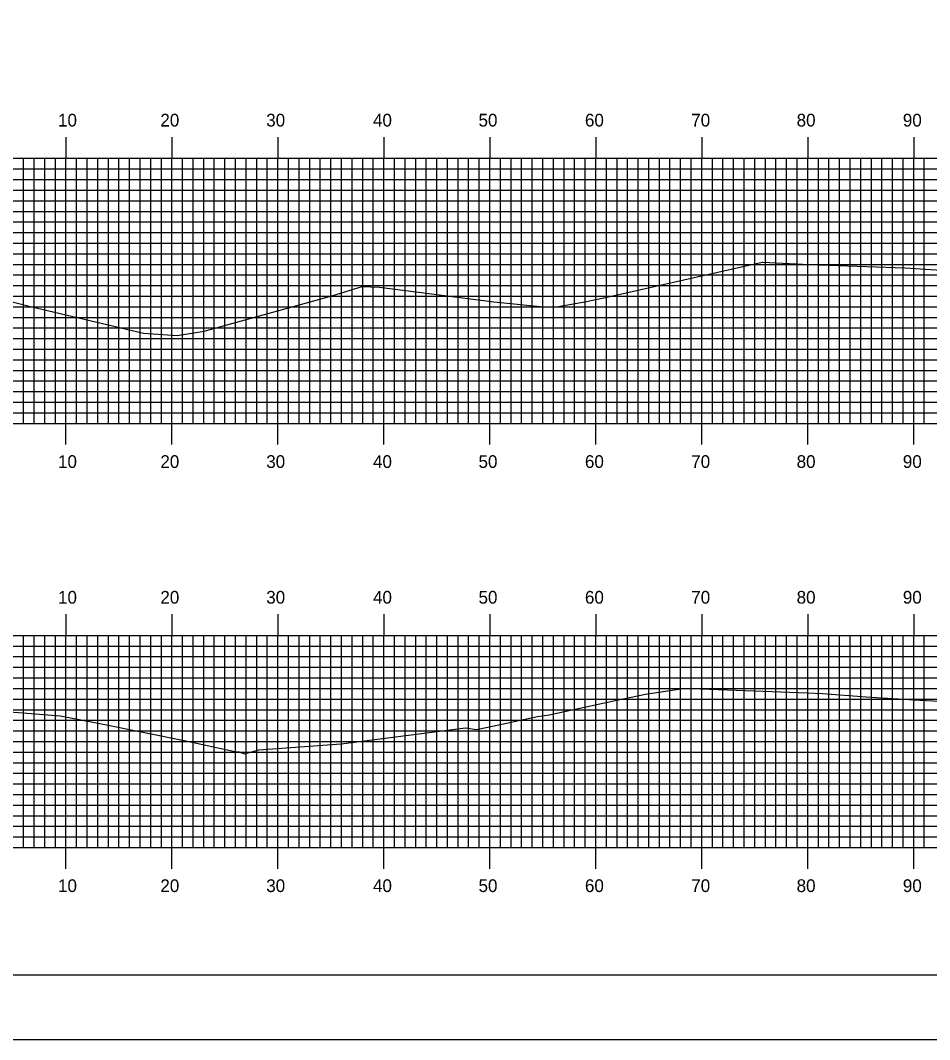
# Model space of a CAD drawing. Extents: x 855468 to 855811, y 366605 to 366825.
# Drawn here: x 855639.3 to 855725.1, y 366604.9 to 366701.1 of the extents above; entities that cross this region are included whole.
import ezdxf

# ---------------------------------------------------------------- set-up
doc = ezdxf.new("R2010")
doc.units = 0
for name, color, linetype in [('BORDER', 7, 'Continuous'), ('H_V ANNOTATION', 7, 'Continuous'), ('M_Roadway_Centerline', 7, 'Continuous'), ('MAJOR', 7, 'Continuous'), ('MINOR', 7, 'Continuous'), ('PLOT BOUNDARY', 7, 'Continuous'), ('S_Roadway_Centerline', 7, 'Continuous')]:
    doc.layers.add(name, color=color, linetype=linetype)

msp = doc.modelspace()

# ---------------------------------------------------------------- linework, layer by layer
at = {"layer": 'BORDER'}
msp.add_lwpolyline([(855483.982, 366611.055), (855803.982, 366611.055), (855803.982, 366821.055), (855483.982, 366821.055)], close=True, dxfattribs=at)
at = {"layer": 'MAJOR'}
for p, q in [((855643.582, 366690.059), (855643.582, 366688.055)), ((855653.582, 366690.059), (855653.582, 366688.055)), ((855663.582, 366690.059), (855663.582, 366688.055)), ((855673.582, 366690.059), (855673.582, 366688.055)), ((855683.582, 366690.059), (855683.582, 366688.055)), ((855693.582, 366690.059), (855693.582, 366688.055)), ((855703.582, 366690.059), (855703.582, 366688.055)), ((855713.582, 366690.059), (855713.582, 366688.055)), ((855723.582, 366690.059), (855723.582, 366688.055)), ((855493.582, 366688.055), (855773.582, 366688.055)), ((855493.582, 366688.055), (855773.582, 366688.055)), ((855643.582, 366663.055), (855643.582, 366688.055)), ((855653.582, 366663.055), (855653.582, 366688.055)), ((855663.582, 366663.055), (855663.582, 366688.055)), ((855673.582, 366663.055), (855673.582, 366688.055)), ((855683.582, 366663.055), (855683.582, 366688.055)), ((855693.582, 366663.055), (855693.582, 366688.055)), ((855703.582, 366663.055), (855703.582, 366688.055)), ((855713.582, 366663.055), (855713.582, 366688.055)), ((855723.582, 366663.055), (855723.582, 366688.055)), ((855493.582, 366683.055), (855773.582, 366683.055)), ((855493.582, 366678.055), (855773.582, 366678.055)), ((855493.582, 366673.055), (855773.582, 366673.055)), ((855493.582, 366668.055), (855773.582, 366668.055)), ((855493.582, 366663.055), (855773.582, 366663.055)), ((855493.582, 366663.055), (855773.582, 366663.055)), ((855643.582, 366661.051), (855643.582, 366663.055)), ((855653.582, 366661.051), (855653.582, 366663.055)), ((855663.582, 366661.051), (855663.582, 366663.055)), ((855673.582, 366661.051), (855673.582, 366663.055)), ((855683.582, 366661.051), (855683.582, 366663.055)), ((855693.582, 366661.051), (855693.582, 366663.055)), ((855703.582, 366661.051), (855703.582, 366663.055)), ((855713.582, 366661.051), (855713.582, 366663.055)), ((855723.582, 366661.051), (855723.582, 366663.055)), ((855643.582, 366645.059), (855643.582, 366643.055)), ((855653.582, 366645.059), (855653.582, 366643.055)), ((855663.582, 366645.059), (855663.582, 366643.055)), ((855673.582, 366645.059), (855673.582, 366643.055)), ((855683.582, 366645.059), (855683.582, 366643.055)), ((855693.582, 366645.059), (855693.582, 366643.055)), ((855703.582, 366645.059), (855703.582, 366643.055)), ((855713.582, 366645.059), (855713.582, 366643.055)), ((855723.582, 366645.059), (855723.582, 366643.055)), ((855493.582, 366643.055), (855773.582, 366643.055)), ((855493.582, 366643.055), (855773.582, 366643.055)), ((855643.582, 366623.055), (855643.582, 366643.055)), ((855653.582, 366623.055), (855653.582, 366643.055)), ((855663.582, 366623.055), (855663.582, 366643.055)), ((855673.582, 366623.055), (855673.582, 366643.055)), ((855683.582, 366623.055), (855683.582, 366643.055)), ((855693.582, 366623.055), (855693.582, 366643.055)), ((855703.582, 366623.055), (855703.582, 366643.055)), ((855713.582, 366623.055), (855713.582, 366643.055)), ((855723.582, 366623.055), (855723.582, 366643.055)), ((855493.582, 366638.055), (855773.582, 366638.055)), ((855493.582, 366633.055), (855773.582, 366633.055)), ((855493.582, 366628.055), (855773.582, 366628.055)), ((855493.582, 366623.055), (855773.582, 366623.055)), ((855493.582, 366623.055), (855773.582, 366623.055)), ((855643.582, 366621.051), (855643.582, 366623.055)), ((855653.582, 366621.051), (855653.582, 366623.055)), ((855663.582, 366621.051), (855663.582, 366623.055)), ((855673.582, 366621.051), (855673.582, 366623.055)), ((855683.582, 366621.051), (855683.582, 366623.055)), ((855693.582, 366621.051), (855693.582, 366623.055)), ((855703.582, 366621.051), (855703.582, 366623.055)), ((855713.582, 366621.051), (855713.582, 366623.055)), ((855723.582, 366621.051), (855723.582, 366623.055))]:
    msp.add_line(p, q, dxfattribs=at)
at = {"layer": 'MINOR'}
for p, q in [((855639.582, 366663.055), (855639.582, 366688.055)), ((855640.582, 366663.055), (855640.582, 366688.055)), ((855641.582, 366663.055), (855641.582, 366688.055)), ((855642.582, 366663.055), (855642.582, 366688.055)), ((855644.582, 366663.055), (855644.582, 366688.055)), ((855645.582, 366663.055), (855645.582, 366688.055)), ((855646.582, 366663.055), (855646.582, 366688.055)), ((855647.582, 366663.055), (855647.582, 366688.055)), ((855648.582, 366663.055), (855648.582, 366688.055)), ((855649.582, 366663.055), (855649.582, 366688.055)), ((855650.582, 366663.055), (855650.582, 366688.055)), ((855651.582, 366663.055), (855651.582, 366688.055)), ((855652.582, 366663.055), (855652.582, 366688.055)), ((855654.582, 366663.055), (855654.582, 366688.055)), ((855655.582, 366663.055), (855655.582, 366688.055)), ((855656.582, 366663.055), (855656.582, 366688.055)), ((855657.582, 366663.055), (855657.582, 366688.055)), ((855658.582, 366663.055), (855658.582, 366688.055)), ((855659.582, 366663.055), (855659.582, 366688.055)), ((855660.582, 366663.055), (855660.582, 366688.055)), ((855661.582, 366663.055), (855661.582, 366688.055)), ((855662.582, 366663.055), (855662.582, 366688.055)), ((855664.582, 366663.055), (855664.582, 366688.055)), ((855665.582, 366663.055), (855665.582, 366688.055)), ((855666.582, 366663.055), (855666.582, 366688.055)), ((855667.582, 366663.055), (855667.582, 366688.055)), ((855668.582, 366663.055), (855668.582, 366688.055)), ((855669.582, 366663.055), (855669.582, 366688.055)), ((855670.582, 366663.055), (855670.582, 366688.055)), ((855671.582, 366663.055), (855671.582, 366688.055)), ((855672.582, 366663.055), (855672.582, 366688.055)), ((855674.582, 366663.055), (855674.582, 366688.055)), ((855675.582, 366663.055), (855675.582, 366688.055)), ((855676.582, 366663.055), (855676.582, 366688.055)), ((855677.582, 366663.055), (855677.582, 366688.055)), ((855678.582, 366663.055), (855678.582, 366688.055)), ((855679.582, 366663.055), (855679.582, 366688.055)), ((855680.582, 366663.055), (855680.582, 366688.055)), ((855681.582, 366663.055), (855681.582, 366688.055)), ((855682.582, 366663.055), (855682.582, 366688.055)), ((855684.582, 366663.055), (855684.582, 366688.055)), ((855685.582, 366663.055), (855685.582, 366688.055)), ((855686.582, 366663.055), (855686.582, 366688.055)), ((855687.582, 366663.055), (855687.582, 366688.055)), ((855688.582, 366663.055), (855688.582, 366688.055)), ((855689.582, 366663.055), (855689.582, 366688.055)), ((855690.582, 366663.055), (855690.582, 366688.055)), ((855691.582, 366663.055), (855691.582, 366688.055)), ((855692.582, 366663.055), (855692.582, 366688.055)), ((855694.582, 366663.055), (855694.582, 366688.055)), ((855695.582, 366663.055), (855695.582, 366688.055)), ((855696.582, 366663.055), (855696.582, 366688.055)), ((855697.582, 366663.055), (855697.582, 366688.055)), ((855698.582, 366663.055), (855698.582, 366688.055)), ((855699.582, 366663.055), (855699.582, 366688.055)), ((855700.582, 366663.055), (855700.582, 366688.055)), ((855701.582, 366663.055), (855701.582, 366688.055)), ((855702.582, 366663.055), (855702.582, 366688.055)), ((855704.582, 366663.055), (855704.582, 366688.055)), ((855705.582, 366663.055), (855705.582, 366688.055)), ((855706.582, 366663.055), (855706.582, 366688.055)), ((855707.582, 366663.055), (855707.582, 366688.055)), ((855708.582, 366663.055), (855708.582, 366688.055)), ((855709.582, 366663.055), (855709.582, 366688.055)), ((855710.582, 366663.055), (855710.582, 366688.055)), ((855711.582, 366663.055), (855711.582, 366688.055)), ((855712.582, 366663.055), (855712.582, 366688.055)), ((855714.582, 366663.055), (855714.582, 366688.055)), ((855715.582, 366663.055), (855715.582, 366688.055)), ((855716.582, 366663.055), (855716.582, 366688.055)), ((855717.582, 366663.055), (855717.582, 366688.055)), ((855718.582, 366663.055), (855718.582, 366688.055)), ((855719.582, 366663.055), (855719.582, 366688.055)), ((855720.582, 366663.055), (855720.582, 366688.055)), ((855721.582, 366663.055), (855721.582, 366688.055)), ((855722.582, 366663.055), (855722.582, 366688.055)), ((855724.582, 366663.055), (855724.582, 366688.055)), ((855493.582, 366687.055), (855773.582, 366687.055)), ((855493.582, 366686.055), (855773.582, 366686.055)), ((855493.582, 366685.055), (855773.582, 366685.055)), ((855493.582, 366684.055), (855773.582, 366684.055)), ((855493.582, 366682.055), (855773.582, 366682.055)), ((855493.582, 366681.055), (855773.582, 366681.055)), ((855493.582, 366680.055), (855773.582, 366680.055)), ((855493.582, 366679.055), (855773.582, 366679.055)), ((855493.582, 366677.055), (855773.582, 366677.055)), ((855493.582, 366676.055), (855773.582, 366676.055)), ((855493.582, 366675.055), (855773.582, 366675.055)), ((855493.582, 366674.055), (855773.582, 366674.055)), ((855493.582, 366672.055), (855773.582, 366672.055)), ((855493.582, 366671.055), (855773.582, 366671.055)), ((855493.582, 366670.055), (855773.582, 366670.055)), ((855493.582, 366669.055), (855773.582, 366669.055)), ((855493.582, 366667.055), (855773.582, 366667.055)), ((855493.582, 366666.055), (855773.582, 366666.055)), ((855493.582, 366665.055), (855773.582, 366665.055)), ((855493.582, 366664.055), (855773.582, 366664.055)), ((855639.582, 366623.055), (855639.582, 366643.055)), ((855640.582, 366623.055), (855640.582, 366643.055)), ((855641.582, 366623.055), (855641.582, 366643.055)), ((855642.582, 366623.055), (855642.582, 366643.055)), ((855644.582, 366623.055), (855644.582, 366643.055)), ((855645.582, 366623.055), (855645.582, 366643.055)), ((855646.582, 366623.055), (855646.582, 366643.055)), ((855647.582, 366623.055), (855647.582, 366643.055)), ((855648.582, 366623.055), (855648.582, 366643.055)), ((855649.582, 366623.055), (855649.582, 366643.055)), ((855650.582, 366623.055), (855650.582, 366643.055)), ((855651.582, 366623.055), (855651.582, 366643.055)), ((855652.582, 366623.055), (855652.582, 366643.055)), ((855654.582, 366623.055), (855654.582, 366643.055)), ((855655.582, 366623.055), (855655.582, 366643.055)), ((855656.582, 366623.055), (855656.582, 366643.055)), ((855657.582, 366623.055), (855657.582, 366643.055)), ((855658.582, 366623.055), (855658.582, 366643.055)), ((855659.582, 366623.055), (855659.582, 366643.055)), ((855660.582, 366623.055), (855660.582, 366643.055)), ((855661.582, 366623.055), (855661.582, 366643.055)), ((855662.582, 366623.055), (855662.582, 366643.055)), ((855664.582, 366623.055), (855664.582, 366643.055)), ((855665.582, 366623.055), (855665.582, 366643.055)), ((855666.582, 366623.055), (855666.582, 366643.055)), ((855667.582, 366623.055), (855667.582, 366643.055)), ((855668.582, 366623.055), (855668.582, 366643.055)), ((855669.582, 366623.055), (855669.582, 366643.055)), ((855670.582, 366623.055), (855670.582, 366643.055)), ((855671.582, 366623.055), (855671.582, 366643.055)), ((855672.582, 366623.055), (855672.582, 366643.055)), ((855674.582, 366623.055), (855674.582, 366643.055)), ((855675.582, 366623.055), (855675.582, 366643.055)), ((855676.582, 366623.055), (855676.582, 366643.055)), ((855677.582, 366623.055), (855677.582, 366643.055)), ((855678.582, 366623.055), (855678.582, 366643.055)), ((855679.582, 366623.055), (855679.582, 366643.055)), ((855680.582, 366623.055), (855680.582, 366643.055)), ((855681.582, 366623.055), (855681.582, 366643.055)), ((855682.582, 366623.055), (855682.582, 366643.055)), ((855684.582, 366623.055), (855684.582, 366643.055)), ((855685.582, 366623.055), (855685.582, 366643.055)), ((855686.582, 366623.055), (855686.582, 366643.055)), ((855687.582, 366623.055), (855687.582, 366643.055)), ((855688.582, 366623.055), (855688.582, 366643.055)), ((855689.582, 366623.055), (855689.582, 366643.055)), ((855690.582, 366623.055), (855690.582, 366643.055)), ((855691.582, 366623.055), (855691.582, 366643.055)), ((855692.582, 366623.055), (855692.582, 366643.055)), ((855694.582, 366623.055), (855694.582, 366643.055)), ((855695.582, 366623.055), (855695.582, 366643.055)), ((855696.582, 366623.055), (855696.582, 366643.055)), ((855697.582, 366623.055), (855697.582, 366643.055)), ((855698.582, 366623.055), (855698.582, 366643.055)), ((855699.582, 366623.055), (855699.582, 366643.055)), ((855700.582, 366623.055), (855700.582, 366643.055)), ((855701.582, 366623.055), (855701.582, 366643.055)), ((855702.582, 366623.055), (855702.582, 366643.055)), ((855704.582, 366623.055), (855704.582, 366643.055)), ((855705.582, 366623.055), (855705.582, 366643.055)), ((855706.582, 366623.055), (855706.582, 366643.055)), ((855707.582, 366623.055), (855707.582, 366643.055)), ((855708.582, 366623.055), (855708.582, 366643.055)), ((855709.582, 366623.055), (855709.582, 366643.055)), ((855710.582, 366623.055), (855710.582, 366643.055)), ((855711.582, 366623.055), (855711.582, 366643.055)), ((855712.582, 366623.055), (855712.582, 366643.055)), ((855714.582, 366623.055), (855714.582, 366643.055)), ((855715.582, 366623.055), (855715.582, 366643.055)), ((855716.582, 366623.055), (855716.582, 366643.055)), ((855717.582, 366623.055), (855717.582, 366643.055)), ((855718.582, 366623.055), (855718.582, 366643.055)), ((855719.582, 366623.055), (855719.582, 366643.055)), ((855720.582, 366623.055), (855720.582, 366643.055)), ((855721.582, 366623.055), (855721.582, 366643.055)), ((855722.582, 366623.055), (855722.582, 366643.055)), ((855724.582, 366623.055), (855724.582, 366643.055)), ((855493.582, 366642.055), (855773.582, 366642.055)), ((855493.582, 366641.055), (855773.582, 366641.055)), ((855493.582, 366640.055), (855773.582, 366640.055)), ((855493.582, 366639.055), (855773.582, 366639.055)), ((855493.582, 366637.055), (855773.582, 366637.055)), ((855493.582, 366636.055), (855773.582, 366636.055)), ((855493.582, 366635.055), (855773.582, 366635.055)), ((855493.582, 366634.055), (855773.582, 366634.055)), ((855493.582, 366632.055), (855773.582, 366632.055)), ((855493.582, 366631.055), (855773.582, 366631.055)), ((855493.582, 366630.055), (855773.582, 366630.055)), ((855493.582, 366629.055), (855773.582, 366629.055)), ((855493.582, 366627.055), (855773.582, 366627.055)), ((855493.582, 366626.055), (855773.582, 366626.055)), ((855493.582, 366625.055), (855773.582, 366625.055)), ((855493.582, 366624.055), (855773.582, 366624.055))]:
    msp.add_line(p, q, dxfattribs=at)
at = {"layer": 'PLOT BOUNDARY'}
msp.add_lwpolyline([(855467.796, 366604.937), (855807.796, 366604.937), (855807.796, 366824.937), (855467.796, 366824.937)], close=True, dxfattribs=at)
at = {"layer": 'S_Roadway_Centerline'}
for points in [[(855636.517, 366675.015), (855640.247, 366674.072), (855650.884, 366671.574), (855654.086, 366671.332), (855656.638, 366671.759), (855668.678, 366675.089), (855671.529, 366675.955), (855673.17, 366675.892), (855683.972, 366674.533), (855688.647, 366674.049), (855689.867, 366674.034), (855692.695, 366674.543), (855694.637, 366674.962), (855696.729, 366675.433), (855709.293, 366678.256), (855709.334, 366678.246), (855713.736, 366678.037), (855722.745, 366677.738), (855723.706, 366677.657), (855730.643, 366677.215)], [(855636.565, 366635.966), (855639.506, 366635.754), (855643.038, 366635.476), (855646.943, 366634.731), (855654.906, 366633.114), (855659.517, 366632.1), (855659.929, 366632.074), (855660.428, 366631.876), (855661.781, 366632.271), (855669.556, 366632.823), (855681.269, 366634.339), (855682.33, 366634.194), (855683.388, 366634.413), (855688.076, 366635.415), (855689.169, 366635.574), (855695.421, 366636.925), (855698.257, 366637.527), (855701.834, 366638.041), (855702.62, 366638.042), (855713.564, 366637.628), (855714.978, 366637.578), (855719.096, 366637.258), (855724.168, 366636.967), (855730.829, 366636.613)]]:
    msp.add_lwpolyline(points, dxfattribs=at)

# ---------------------------------------------------------------- texts
at = {"layer": 'H_V ANNOTATION'}
for s, p in [('10', (855642.833, 366691.055)), ('20', (855652.49, 366691.055)), ('30', (855662.48, 366691.055)), ('40', (855672.555, 366691.055)), ('50', (855682.512, 366691.055)), ('60', (855692.555, 366691.055)), ('70', (855702.587, 366691.055)), ('80', (855712.533, 366691.055)), ('90', (855722.555, 366691.055)), ('10', (855642.833, 366658.855)), ('20', (855652.49, 366658.855)), ('30', (855662.48, 366658.855)), ('40', (855672.555, 366658.855)), ('50', (855682.512, 366658.855)), ('60', (855692.555, 366658.855)), ('70', (855702.587, 366658.855)), ('80', (855712.533, 366658.855)), ('90', (855722.555, 366658.855)), ('10', (855642.833, 366646.055)), ('20', (855652.49, 366646.055)), ('30', (855662.48, 366646.055)), ('40', (855672.555, 366646.055)), ('50', (855682.512, 366646.055)), ('60', (855692.555, 366646.055)), ('70', (855702.587, 366646.055)), ('80', (855712.533, 366646.055)), ('90', (855722.555, 366646.055)), ('10', (855642.833, 366618.855)), ('20', (855652.49, 366618.855)), ('30', (855662.48, 366618.855)), ('40', (855672.555, 366618.855)), ('50', (855682.512, 366618.855)), ('60', (855692.555, 366618.855)), ('70', (855702.587, 366618.855)), ('80', (855712.533, 366618.855)), ('90', (855722.555, 366618.855))]:
    msp.add_text(s, height=1.2, dxfattribs=at).set_placement(p)
at = {"layer": 'M_Roadway_Centerline'}
for s, p in [('C', (855722.74, 366677.738)), ('L', (855722.745, 366677.731)), ('C', (855714.973, 366637.578)), ('L', (855714.978, 366637.571))]:
    msp.add_text(s, height=0.0146, dxfattribs=at).set_placement(p)

doc.saveas('drawing.dxf')
